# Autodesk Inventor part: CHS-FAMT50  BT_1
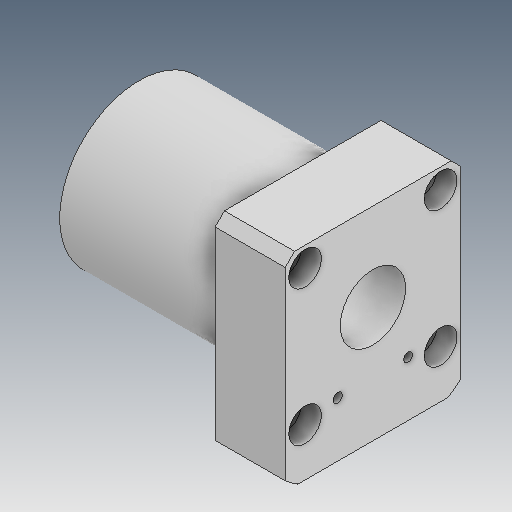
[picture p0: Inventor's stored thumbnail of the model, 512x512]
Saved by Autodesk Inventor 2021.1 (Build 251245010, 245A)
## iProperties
Created: 2019-04
Part Number: CHS-FAMT50  BT_1
Material: Ogólny
Document SubType Name: Modeling
Designer: user
Density: 1 g/cm^3
Appearance: Domyślna
Author: user
Revision Number: ÈÎºÎ
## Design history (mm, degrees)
feature "ÊäÈë1"
node "Bryła1"
